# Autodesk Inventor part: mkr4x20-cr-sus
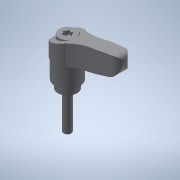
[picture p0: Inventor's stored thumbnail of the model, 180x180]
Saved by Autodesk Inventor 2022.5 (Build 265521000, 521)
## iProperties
Created: 2017-09
Part Number: mkr4x20-cr-sus
Material: 一般
Document SubType Name: Modeling
Designer: imaocorp
Density: 1 g/cm^3
Appearance: 既定
Author: imaocorp
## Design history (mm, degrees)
node "mkr4x20-cr-sus.x_t1"
node "mkr4x20-cr-sus"
node "Base1"
